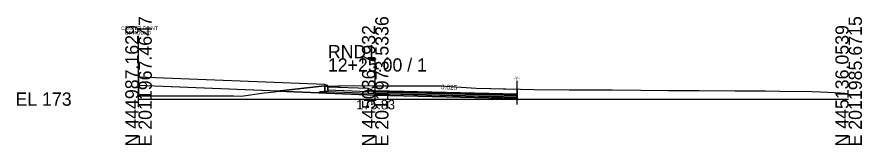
# Model space of a CAD drawing. Extents: x -26 to 153, y -10 to 6017.
# Drawn here: x -25.7 to 152.8, y 4490.3 to 4517.3 of the extents above; entities that cross this region are included whole.
import ezdxf

# ---------------------------------------------------------------- set-up
doc = ezdxf.new("R2010")
doc.units = 0
for name, color, linetype in [('Exist Cross Section Cell', 7, 'Continuous'), ('Exist XS Ground Line', 7, 'Continuous'), ('Prop CMT Conc Surface', 7, 'Continuous'), ('Prop CMT Concrete Structures', 7, 'Continuous'), ('Prop CMT Pvmt Course 1', 7, 'Continuous'), ('Prop CMT Pvmt Course 1 CG', 7, 'Continuous'), ('Prop CMT Pvmt Course 2', 7, 'Continuous'), ('Prop CMT Pvmt Course 3', 7, 'Continuous'), ('Prop CMT Pvmt Surface', 7, 'Continuous'), ('Prop CMT Shear Line', 7, 'Continuous'), ('Prop CMT Shear Line Text', 7, 'Continuous'), ('Prop CMT Slope Grass', 7, 'Continuous'), ('Prop CMT Subgrade Earthwork', 7, 'Continuous'), ('Prop XS Earthwork Shape', 7, 'Continuous'), ('Prop XS SE Text', 7, 'Continuous')]:
    doc.layers.add(name, color=color, linetype=linetype)

msp = doc.modelspace()

# ---------------------------------------------------------------- linework, layer by layer
at = {"layer": 'Exist Cross Section Cell'}
for p, q in [((50, 4500), (50, 4508.6)), ((0, 4500), (50, 4500)), ((50, 4500), (150, 4500))]:
    msp.add_line(p, q, dxfattribs=at)
at = {"layer": 'Exist XS Ground Line'}
msp.add_lwpolyline([(0, 4500.62), (0.42, 4500.62), (2.2, 4500.67), (2.91, 4500.69), (4.43, 4500.67), (5.42, 4500.66), (6.67, 4500.68), (7.92, 4500.7), (8.45, 4500.71), (8.79, 4500.71), (10.46, 4500.69), (11.17, 4500.69), (12.95, 4500.7), (15.65, 4500.69), (16.96, 4500.69), (18.03, 4500.68), (18.39, 4500.68), (19.64, 4500.68), (20.09, 4500.67), (21.7, 4500.64), (26.55, 4501.29), (27.4, 4501.4), (28.69, 4501.54), (29.89, 4501.71), (38.7, 4502.72), (45.47, 4502.87), (50, 4502.83), (51.98, 4502.81), (58.03, 4502.79), (62.93, 4502.83), (63.85, 4502.78), (71.35, 4502.3), (80.71, 4502.06), (83.58, 4502.01), (90.97, 4501.96), (92.46, 4501.95), (100.04, 4501.92), (106.08, 4501.88), (111.86, 4501.79), (118.45, 4501.8), (125.93, 4501.75), (132.14, 4501.75), (132.46, 4501.75), (135.49, 4501.65), (142.25, 4501.59), (144.05, 4501.52), (145.59, 4501.43), (148.26, 4501.3), (150, 4501.2)], dxfattribs=at)
at = {"layer": 'Prop CMT Conc Surface'}
for points in [[(40, 4502.73), (39.96, 4502.84), (39.85, 4502.88), (39.34, 4503.07)], [(40, 4502.57), (40, 4502.73)], [(50, 4501.77), (49.25, 4501.79), (49.25, 4501.96), (48.5, 4502.21)]]:
    msp.add_lwpolyline(points, dxfattribs=at)
at = {"layer": 'Prop CMT Concrete Structures'}
for points in [[(40, 4502.73), (39.96, 4502.84), (39.85, 4502.88), (39.34, 4503.07)], [(39.34, 4503.07), (39.34, 4501.57)], [(40, 4502.57), (40, 4502.73)], [(39.34, 4501.57), (40, 4501.57)], [(40, 4501.57), (40, 4502.57)], [(40, 4502.57), (40, 4501.98)], [(48.5, 4502.21), (40, 4502.55)], [(40, 4501.96), (48.5, 4501.62)], [(50, 4501.77), (49.25, 4501.79), (49.25, 4501.96), (48.5, 4502.21)], [(48.5, 4502.21), (48.5, 4501.23)], [(48.5, 4501.62), (48.5, 4502.21)], [(48.5, 4501.23), (50, 4501.19)], [(50, 4501.19), (50, 4501.77)]]:
    msp.add_lwpolyline(points, dxfattribs=at)
at = {"layer": 'Prop CMT Pvmt Course 1'}
for points in [[(50, 4501.77), (80, 4501.02)], [(50, 4501.52), (50, 4501.77)], [(80, 4500.77), (50, 4501.52)], [(80, 4501.02), (80, 4500.77)]]:
    msp.add_lwpolyline(points, dxfattribs=at)
msp.add_lwpolyline([(50, 4501.52), (50, 4501.65), (50, 4501.65), (50, 4501.52)], close=True, dxfattribs=at)
at = {"layer": 'Prop CMT Pvmt Course 1 CG'}
for points in [[(50, 4500.85), (50, 4501.19)], [(80, 4500.1), (80, 4500.43)]]:
    msp.add_lwpolyline(points, dxfattribs=at)
at = {"layer": 'Prop CMT Pvmt Course 2'}
for points in [[(50, 4501.19), (50, 4501.52)], [(50, 4501.52), (80, 4500.77)], [(80, 4500.44), (50, 4501.19)], [(80, 4500.77), (80, 4500.43)]]:
    msp.add_lwpolyline(points, dxfattribs=at)
at = {"layer": 'Prop CMT Pvmt Course 3'}
for points in [[(40, 4501.57), (48.5, 4501.23)], [(50, 4501.19), (80, 4500.44)], [(50, 4500.85), (50, 4501.19)], [(80, 4500.1), (50, 4500.85)], [(80, 4500.43), (80, 4500.1)]]:
    msp.add_lwpolyline(points, dxfattribs=at)
at = {"layer": 'Prop CMT Pvmt Surface'}
msp.add_lwpolyline([(50, 4501.77), (80, 4501.02)], dxfattribs=at)
at = {"layer": 'Prop CMT Shear Line'}
for p, q in [((0, 4498.31), (0, 4513.31)), ((80, 4498.85), (80, 4503.86))]:
    msp.add_line(p, q, dxfattribs=at)
at = {"layer": 'Prop CMT Slope Grass'}
for p, q in [((39.34, 4503.05), (0, 4504.62)), ((38.06, 4501.33), (0, 4502.86))]:
    msp.add_line(p, q, dxfattribs=at)
at = {"layer": 'Prop CMT Subgrade Earthwork'}
for p, q in [((0, 4504.62), (0, 4500.62)), ((38.34, 4501.61), (38.06, 4501.33)), ((80, 4500.1), (80, 4502.08))]:
    msp.add_line(p, q, dxfattribs=at)
for points in [[(38.06, 4501.33), (50, 4500.85)], [(38.34, 4501.61), (39.34, 4501.57)], [(50, 4500.85), (80, 4500.1)]]:
    msp.add_lwpolyline(points, dxfattribs=at)
at = {"layer": 'Prop XS Earthwork Shape'}
for points in [[(7.92, 4500.7), (8.45, 4500.71), (8.79, 4500.71), (10.46, 4500.69), (11.17, 4500.69), (12.95, 4500.7), (15.65, 4500.69), (16.96, 4500.69), (18.03, 4500.68), (18.39, 4500.68), (19.64, 4500.68), (20.09, 4500.67), (21.7, 4500.64), (26.55, 4501.29), (27.4, 4501.4), (28.69, 4501.54), (29.6, 4501.67), (0, 4502.86), (0, 4500.62), (0.42, 4500.62), (2.2, 4500.67), (2.91, 4500.69), (4.43, 4500.67), (5.42, 4500.66), (6.67, 4500.68)], [(38.34, 4501.61), (39.34, 4501.57), (39.34, 4502.73), (38.7, 4502.72), (29.89, 4501.71), (29.6, 4501.67), (38.06, 4501.33)], [(39.34, 4502.73), (39.99, 4502.75), (40, 4502.73), (40, 4502.57), (40, 4502.55), (40, 4501.98), (40, 4501.96), (40, 4501.57), (39.34, 4501.57)], [(49.25, 4501.96), (48.5, 4502.21), (40, 4502.55), (40, 4502.57), (40, 4502.73), (39.99, 4502.75), (45.47, 4502.87), (50, 4502.83), (51.98, 4502.81), (58.03, 4502.79), (62.93, 4502.83), (63.85, 4502.78), (71.35, 4502.3), (80, 4502.08), (80, 4501.02), (50, 4501.77), (49.25, 4501.79)], [(48.5, 4501.23), (50, 4501.19), (50, 4501.77), (80, 4501.02), (80, 4500.1), (50, 4500.85), (38.06, 4501.33), (38.34, 4501.61), (39.34, 4501.57), (40, 4501.57), (40, 4501.96), (48.5, 4501.62)], [(48.5, 4501.62), (48.5, 4502.21), (40, 4502.55), (40, 4501.98), (40, 4501.96)], [(48.5, 4501.62), (48.5, 4502.21), (49.25, 4501.96), (49.25, 4501.79), (50, 4501.77), (50, 4501.19), (48.5, 4501.23)]]:
    msp.add_lwpolyline(points, close=True, dxfattribs=at)

# ---------------------------------------------------------------- texts
at = {"layer": 'Exist Cross Section Cell'}
for s, p in [('E 2011967.4647', (2.8, 4490)), ('E 2011973.5336', (52.8, 4490)), ('E 2011985.6715', (152.8, 4490)), ('N 444987.1629', (0, 4490)), ('N 445036.7932', (50, 4490)), ('N 445136.0539', (150, 4490))]:
    msp.add_text(s, height=2.8, rotation=90, dxfattribs=at).set_placement(p)
for s, p in [('RND1', (40, 4508.6)), ('12+25.00 / 1', (40, 4505.8)), ('EL 173', (-26, 4498.6))]:
    msp.add_text(s, height=2.8, dxfattribs=at).set_placement(p)
at = {"layer": 'Exist XS Ground Line'}
msp.add_text('175.83', height=2, dxfattribs=at).set_placement((45.99, 4497.83))
at = {"layer": 'Prop CMT Shear Line Text'}
for s, p in [('CENTER POINT', (-3.64, 4514.57)), ('OF ROUND', (-2.88, 4513.59)), ('-Y-', (79.21, 4503.97))]:
    msp.add_text(s, height=0.75, dxfattribs=at).set_placement(p)
at = {"layer": 'Prop XS SE Text'}
msp.add_text('0.025', height=1, rotation=358.5613, dxfattribs=at).set_placement((63.87, 4502.05))

doc.saveas('drawing.dxf')
